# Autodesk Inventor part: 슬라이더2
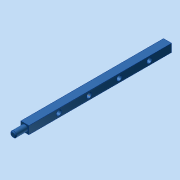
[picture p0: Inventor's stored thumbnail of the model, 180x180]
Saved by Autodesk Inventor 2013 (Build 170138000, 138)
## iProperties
Company: 한국ATC센터
Created: 2015-04
Part Number: 슬라이더2
Document SubType Name: Modeling
Designer: KYOUNG IL JANG
Density: 1 g/cm^3
Material: 일반
Mass: 8.7906 g
Surface Area: 52.3143 cm^2
Volume: 8.7906 cm^3
Author: KYOUNG IL JANG
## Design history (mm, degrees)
sketch "스케치3"
  geometry: L1 (4, 142)-(-4, 142); L2 (-4, 142)-(-4, 0); L3 (-4, 0)-(4, 0); L4 (4, 0)-(4, 142); 3 further points
  constraints: 8 end point, 2 coincident, 2 parallel, 1 horizontal, 1 midpoint, 1 perpendicular
  dimensions: "d5" = 8 distance of L1.start L1.end; "d6" = 142 distance of L1.end L2.end
extrude "돌출3" new body sketch "스케치3" stored distance "d7" = 8; taper "d8" = 0 deg
sketch "스케치4"
  geometry: L1 (8, 0)-(0, 0) reference; 3 further points
  constraints: 1 midpoint, 1 vertical alignment
  dimensions: "d9" = 30 distance of point (4, 30) point (4, 0)
hole "구멍1" sketch "스케치4" at (4, 30) diameter "d10" = 5; stored, may be unused: countersink angle "d14" = 90 deg, drill point angle "d16" = 118 deg; dims "d11" = 6, "d12" = 4, "d13" = 2, "d15" = 8
sketch "스케치5"
  geometry: C1 r 3 at (4, -4); 1 further point
  constraints: 1 centre point, 1 coincident
  dimensions: "d20" = 6 diameter of C1
extrude "돌출4" join sketch "스케치5" distance "d21" = 12; taper "d22" = 0 deg
chamfer "모따기1" distance "d23" = 1; stored, may be unused: second distance "d24" = 2, angle "d25" = 45 deg
node "작업 평면2"
  node "작업축1"
node "솔리드1"
pattern_linear "직사각형 패턴1" dims "d19" = 30
node "솔리드2"
other parameters: "d26" = 0
